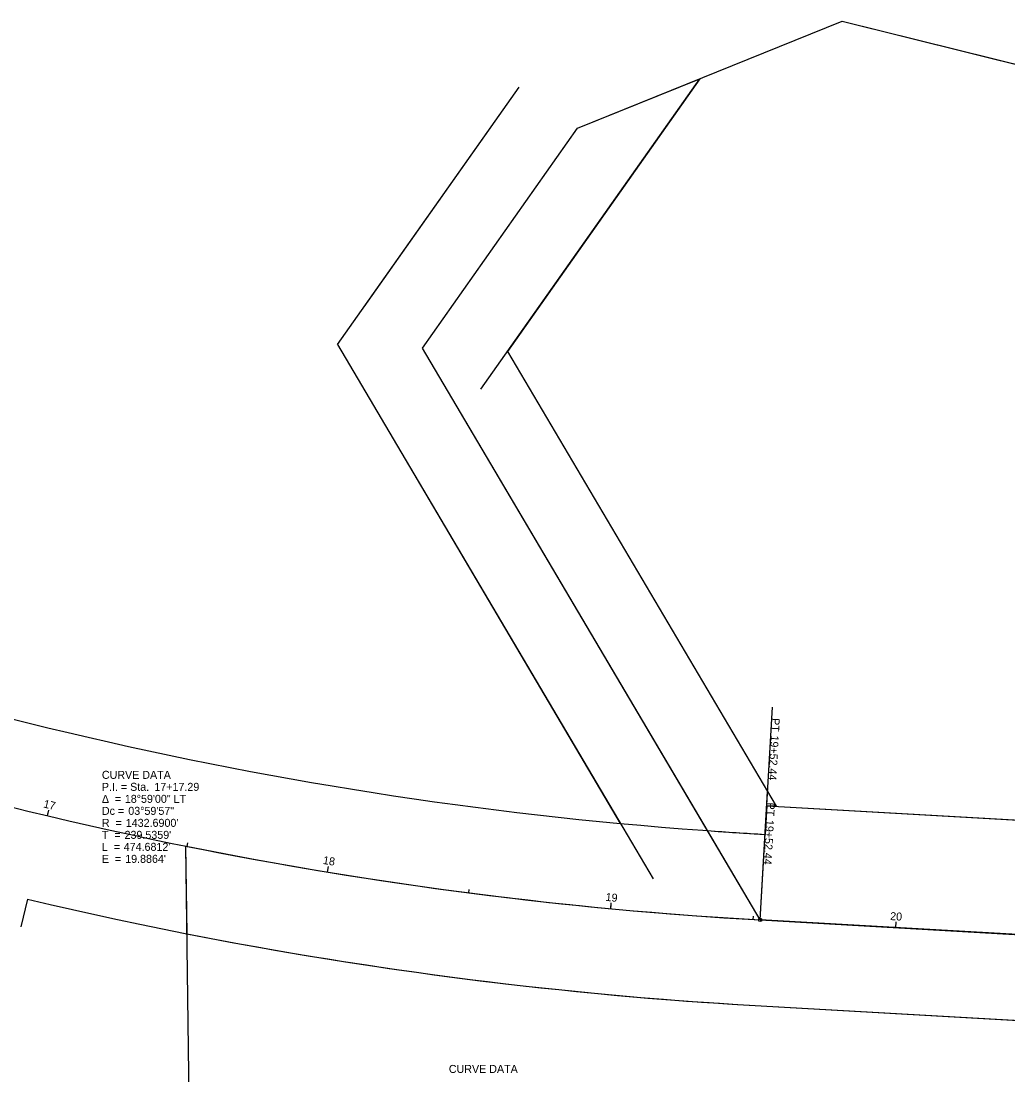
# Model space of a CAD drawing. Extents: x 2273111 to 2279616, y 652916 to 655718.
# Drawn here: x 2274199.4 to 2274544.8, y 654659.4 to 655028.2 of the extents above; entities that cross this region are included whole.
import ezdxf

# ---------------------------------------------------------------- set-up
doc = ezdxf.new("R2010")
doc.units = 0
for name, color, linetype in [('DV_X_Property_Line', 7, 'Continuous'), ('RW_X_CL', 7, 'Continuous'), ('RW_X_CL_1000_Curve_Data', 7, 'Continuous'), ('RW_X_CL_1000_Stations', 7, 'Continuous'), ('RW_X_CL_100_Curve_Data', 7, 'Continuous'), ('RW_X_CL_100_Stations', 7, 'Continuous'), ('RW_X_CL_500_Curve_Data', 7, 'Continuous'), ('RW_X_CL_500_Stations', 7, 'Continuous'), ('RW_X_Esmt_SH', 7, 'Continuous'), ('SC_Scratch4', 7, 'Continuous'), ('SC_Scratch5', 7, 'Continuous')]:
    doc.layers.add(name, color=color, linetype=linetype)

msp = doc.modelspace()

# ---------------------------------------------------------------- linework, layer by layer
at = {"layer": 'DV_X_Property_Line'}
for p, q in [((2274394.14, 654990.65), (2274486.83, 655028.17)), ((2274486.83, 655028.17), (2274732.19, 654967.18)), ((2274256.97, 654739.46), (2274264.62, 654176.5))]:
    msp.add_line(p, q, dxfattribs=at)
at = {"layer": 'RW_X_CL'}
for p, q in [((2274339.92, 654913.73), (2274394.14, 654990.65)), ((2274458.12, 654713.61), (2274339.92, 654913.73)), ((2274458.12, 654713.61), (2274687.5, 654700.52))]:
    msp.add_line(p, q, dxfattribs=at)
msp.add_arc((2274539.73, 656143.97), 1432.69, 247.75095, 266.73428, dxfattribs=at)
at = {"layer": 'RW_X_CL_1000_Stations'}
for p, q in [((2274458.12, 654713.61), (2274460.68, 654758.54)), ((2274505.6, 654710.9), (2274505.72, 654712.9))]:
    msp.add_line(p, q, dxfattribs=at)
msp.add_circle((2274458.12, 654713.61), 0.6, dxfattribs=at)
at = {"layer": 'RW_X_CL_100_Stations'}
for p, q in [((2274458.12, 654713.61), (2274462.38, 654788.08)), ((2274208.65, 654750.06), (2274209.12, 654752.01)), ((2274257.49, 654739.36), (2274257.73, 654740.53)), ((2274306.67, 654730.36), (2274307, 654732.34)), ((2274356.14, 654723.09), (2274356.29, 654724.28)), ((2274405.83, 654717.55), (2274406.02, 654719.54)), ((2274455.68, 654713.75), (2274455.75, 654714.95)), ((2274505.6, 654710.9), (2274505.72, 654712.9))]:
    msp.add_line(p, q, dxfattribs=at)
msp.add_circle((2274458.12, 654713.61), 0.6, dxfattribs=at)
at = {"layer": 'RW_X_CL_500_Stations'}
for p, q in [((2274458.12, 654713.61), (2274460.68, 654758.54)), ((2274208.65, 654750.06), (2274208.93, 654751.23)), ((2274306.67, 654730.36), (2274306.87, 654731.55)), ((2274405.83, 654717.55), (2274405.94, 654718.75)), ((2274505.6, 654710.9), (2274505.72, 654712.9))]:
    msp.add_line(p, q, dxfattribs=at)
msp.add_circle((2274458.12, 654713.61), 0.6, dxfattribs=at)
at = {"layer": 'RW_X_Esmt_SH'}
for p, q in [((2274310.18, 654914.93), (2274373.71, 655005.05)), ((2274319.49, 654928.13), (2274373.71, 655005.05)), ((2274360.35, 654899.32), (2274414.58, 654976.24)), ((2274369.66, 654912.53), (2274414.58, 654976.24)), ((2274310.18, 654914.93), (2274409.14, 654747.37)), ((2274369.66, 654912.53), (2274463.68, 654753.36)), ((2274369.66, 654912.53), (2274463.68, 654753.36)), ((2274326.61, 654887.1), (2274420.62, 654727.93)), ((2274459.83, 654743.56), (2274460.4, 654753.54)), ((2274460.4, 654753.54), (2274689.78, 654740.45)), ((2274199.4, 654711.15), (2274201.71, 654720.88)), ((2274456.41, 654683.66), (2274685.8, 654670.57))]:
    msp.add_line(p, q, dxfattribs=at)
for radius, start in [(1402.69, 247.75095), (1462.69, 256.63836)]:
    msp.add_arc((2274539.73, 656143.97), radius, start, 266.73428, dxfattribs=at)
at = {"layer": 'SC_Scratch4'}
for p, q in [((2274414.58, 654976.24), (2274436.95, 655007.97)), ((2274256.97, 654739.46), (2274257.39, 654708.79)), ((2274687.5, 654700.52), (2274458.12, 654713.61))]:
    msp.add_line(p, q, dxfattribs=at)
for points in [[(2274439.66, 654744.86), (2274339.92, 654913.73), (2274394.14, 654990.65), (2274436.95, 655007.97), (2274369.66, 654912.53), (2274463.68, 654753.36), (2274460.4, 654753.54), (2274459.83, 654743.56)], [(2274459.83, 654743.56), (2274460.4, 654753.54), (2274689.78, 654740.45)], [(2274687.5, 654700.52), (2274458.12, 654713.61), (2274439.66, 654744.86)], [(2274456.41, 654683.66), (2274685.8, 654670.57), (2274685.51, 654665.58)]]:
    msp.add_lwpolyline(points, dxfattribs=at)
for radius, start in [(1402.69, 265.9089), (1402.69, 265.9089), (1432.69, 258.61717), (1462.69, 258.87029)]:
    msp.add_arc((2274539.73, 656143.97), radius, start, 266.73428, dxfattribs=at)
at = {"layer": 'SC_Scratch5'}
msp.add_lwpolyline([(2274687.5, 654700.52), (2274458.12, 654713.61), (2274339.92, 654913.73), (2274394.14, 654990.65), (2274486.83, 655028.17), (2274732.19, 654967.18), (2274766.64, 654697.37)], dxfattribs=at)

# ---------------------------------------------------------------- texts
at = {"layer": 'RW_X_CL_1000_Curve_Data'}
for s, p in [('CURVE DATA', (2274227.69, 654762.98)), ('P.I. = Sta. ', (2274227.69, 654758.78)), ('17+17.29', (2274246.06, 654758.78)), ('Δ  = ', (2274227.69, 654754.58)), ('18°59\'00" LT', (2274235.72, 654754.58)), ('Dc = ', (2274227.69, 654750.38)), ('03°59\'57"', (2274236.93, 654750.38)), ("1432.6900'", (2274236.06, 654746.18)), ('R  = ', (2274227.69, 654746.18)), ('T  = ', (2274227.69, 654741.98)), ("239.5359'", (2274235.63, 654741.98)), ('L  = ', (2274227.69, 654737.78)), ("474.6812'", (2274235.34, 654737.78)), ('E  = ', (2274227.69, 654733.58)), ("19.8864'", (2274235.85, 654733.58))]:
    msp.add_text(s, height=2.8, dxfattribs=at).set_placement(p)
at = {"layer": 'RW_X_CL_1000_Stations'}
for s, rotation, p in [('PT', 266.7343, (2274460.51, 654754.77)), ('19+52.44', 266.7343, (2274460.17, 654748.69)), ('20', 356.7343, (2274503.56, 654713.57))]:
    msp.add_text(s, height=2.8, rotation=rotation, dxfattribs=at).set_placement(p)
at = {"layer": 'RW_X_CL_100_Curve_Data'}
msp.add_text('CURVE DATA', height=2.8, dxfattribs=at).set_placement((2274349.14, 654660.06))
at = {"layer": 'RW_X_CL_100_Stations'}
for s, rotation, p in [('PT', 266.7343, (2274462.21, 654784.31)), ('19+52.44', 266.7343, (2274461.87, 654778.23)), ('17', 346.6388, (2274207.04, 654753.01)), ('18', 350.638, (2274304.93, 654733.23)), ('19', 354.6371, (2274403.91, 654720.29)), ('20', 356.7343, (2274503.56, 654713.57))]:
    msp.add_text(s, height=2.8, rotation=rotation, dxfattribs=at).set_placement(p)
at = {"layer": 'RW_X_CL_500_Curve_Data'}
for s, p in [('CURVE DATA', (2274227.69, 654762.98)), ('P.I. = Sta. ', (2274227.69, 654758.78)), ('17+17.29', (2274246.06, 654758.78)), ('Δ  = ', (2274227.69, 654754.58)), ('18°59\'00" LT', (2274235.72, 654754.58)), ('Dc = ', (2274227.69, 654750.38)), ('03°59\'57"', (2274236.93, 654750.38)), ("1432.6900'", (2274236.06, 654746.18)), ('R  = ', (2274227.69, 654746.18)), ('T  = ', (2274227.69, 654741.98)), ("239.5359'", (2274235.63, 654741.98)), ('L  = ', (2274227.69, 654737.78)), ("474.6812'", (2274235.34, 654737.78)), ('E  = ', (2274227.69, 654733.58)), ("19.8864'", (2274235.85, 654733.58))]:
    msp.add_text(s, height=2.8, dxfattribs=at).set_placement(p)
at = {"layer": 'RW_X_CL_500_Stations'}
for s, rotation, p in [('PT', 266.7343, (2274460.51, 654754.77)), ('19+52.44', 266.7343, (2274460.17, 654748.69)), ('20', 356.7343, (2274503.56, 654713.57))]:
    msp.add_text(s, height=2.8, rotation=rotation, dxfattribs=at).set_placement(p)

doc.saveas('drawing.dxf')
